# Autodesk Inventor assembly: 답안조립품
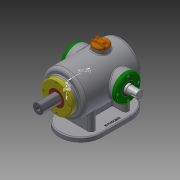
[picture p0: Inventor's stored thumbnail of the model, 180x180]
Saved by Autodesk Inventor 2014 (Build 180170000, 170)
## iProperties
Created: 2017-01
Part Number: 답안조립품
Document SubType Name: Assembly
Designer: user
Author: user
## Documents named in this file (16)
- C:\Users\user\Desktop\370108V1008\답안조립품.iam
- C:\Users\user\Desktop\370108V1008\본체.ipt
- C:\Users\user\Desktop\370108V1008\플레이트.ipt
- C:\Users\user\Desktop\370108V1008\베어링 6205.ipt
- 베어링 6205.ipt
- C:\Users\user\Desktop\370108V1008\축 커버-1.ipt
- C:\Users\user\Desktop\370108V1008\축 커버-2.ipt
- C:\Users\user\Desktop\370108V1008\오일실.ipt
- 오일실.ipt
- C:\Users\user\Desktop\370108V1008\슬라이드 커버.ipt
- C:\Users\user\Desktop\370108V1008\부시.ipt
- C:\Users\user\Desktop\370108V1008\편심축.ipt
- C:\Users\user\Desktop\370108V1008\슬라이드.ipt
- C:\Users\user\Desktop\370108V1008\볼트 M4x0.7.ipt
- C:\Users\user\Desktop\370108V1008\상부 캡.ipt
- C:\Users\user\Desktop\370108V1008\가변스프링.ipt
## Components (14 placed, 3 different names)
1. 플레이트:1 — Insert:1, Insert:2
2. 가변스프링:1 — Mate:3, Mate:4, Mate:6
3. M4x0.7:3 — Insert:12
4. M4x0.7:4
5. M4x0.7:5
6. M4x0.7:6
7. M4x0.7:2 — Insert:13
8. M4x0.7:7
9. M4x0.7:8
10. M4x0.7:9
11. M4x0.7:1 — Insert:14
12. M4x0.7:10
13. M4x0.7:11
14. M4x0.7:12
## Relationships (8: Insert 5, Mate 3)
- Insert:1: 플레이트:1
- Insert:2: 플레이트:1
- Mate:3: 가변스프링:1
- Mate:4: 가변스프링:1
- Mate:6: 가변스프링:1
- Insert:12: M4x0.7:3
- Insert:13: M4x0.7:2
- Insert:14: M4x0.7:1
